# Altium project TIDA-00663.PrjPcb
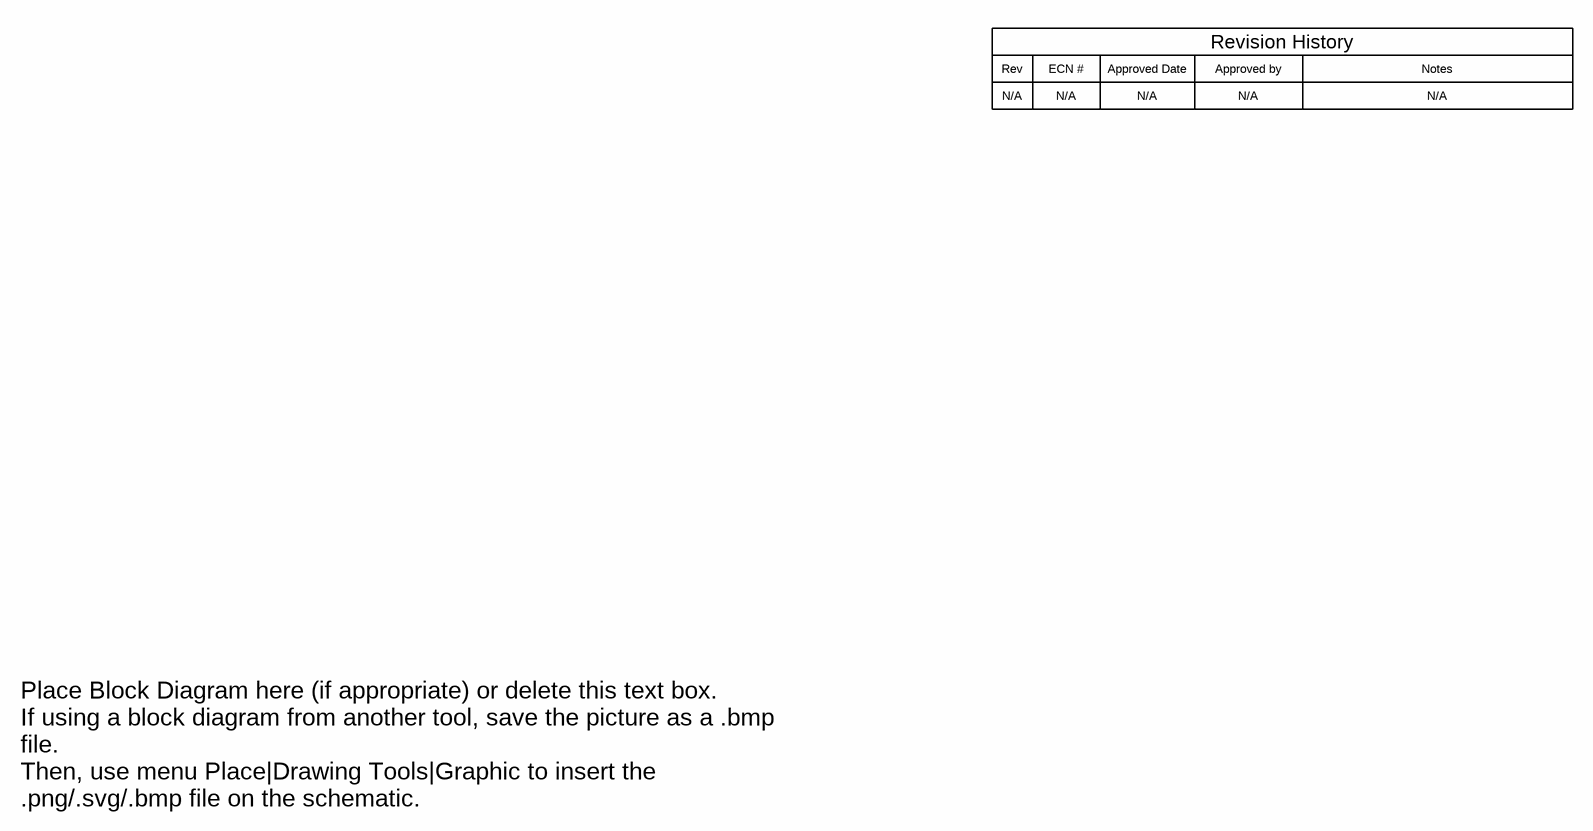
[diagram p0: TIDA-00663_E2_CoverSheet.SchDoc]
CopyrightYear: 2016; PCB_Layout: GCD; PCB_Rev: E2; PRJ_Customer: Public Release; PRJ_Engineer: Matthieu Chevrier; PRJ_Number: TIDA-00663; PRJ_Title: LIDAR; SCH_Rev: E2; TechSupport: http://www.ti.com/support; TID: TIDA-00663
4 sheets, 73 parts. Net scope: global (net labels, ports and power ports of the same name join across sheets).
Board file: TIDA-00663_E2_PCB.PcbDoc
Sheets:
  TIDA-00663_E2_CoverSheet.SchDoc
  TIDA-00663_E2_time_measure_shi.SchDoc
  TIDA-00663_E2_EVM_Hardware.SchDoc
  TIDA-00663_E2_DesignForTest.SchDoc

## Sheet TIDA-00663_E2_CoverSheet.SchDoc
size 431 x 279 mm; Date: Not shown in title block; ApprovedBy: Not shown in title block; CheckedBy: Not shown in title block; Author: Not shown in title block; CompanyName: Not shown in title block; Engineer: Not shown in title block; Organization: Not shown in title block; Address1: Not shown in title block; Address2: Not shown in title block; Address3: Not shown in title block; Address4: Not shown in title block; DocumentNumber: 1; Revision: Use project parameter SCH_Rev; SheetNumber: 1; SheetTotal: 3; PageSetup: Record=PageOptions¦CenterHorizontal=True¦CenterVertical=True¦PrintScale=1.00¦XCorrection=1.00¦YCorrection=1.00¦PrintKind=0¦BorderSize=5000000¦LeftOffset=0¦BottomOffset=0¦Orientation=2¦PaperLength=1000¦PaperWidth=1000¦Scale=100¦PaperSource=15¦PrintQuality=600¦MediaType=1¦DitherType=10¦PaperKind=Letter¦PrintScaleMode=1

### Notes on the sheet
- Rev
- N/A
- ECN #
- Approved Date
- Approved by
- Revision History
- Notes
- Place Block Diagram here (if appropriate) or delete this text box.
  If using a block diagram from another tool, save the picture as a .bmp file.
  Then, use menu Place|Drawing Tools|Graphic to insert the .png/.svg/.bmp file on the schematic.

## Sheet TIDA-00663_E2_time_measure_shi.SchDoc
size 431 x 279 mm; Date: Not shown in title block; ApprovedBy: Not shown in title block; CheckedBy: Not shown in title block; Author: Not shown in title block; CompanyName: Not shown in title block; Engineer: Not shown in title block; Organization: Not shown in title block; Address1: Not shown in title block; Address2: Not shown in title block; Address3: Not shown in title block; Address4: Not shown in title block; DocumentNumber: 1; Revision: Use project parameter SCH_Rev; SheetNumber: 2; SheetTotal: 3; PageSetup: Record=PageOptions¦CenterHorizontal=True¦CenterVertical=True¦PrintScale=0.80¦XCorrection=1.00¦YCorrection=1.00¦PrintKind=0¦BorderSize=5000000¦LeftOffset=0¦BottomOffset=0¦Orientation=2¦PaperLength=4200¦PaperWidth=2970¦Scale=100¦PaperSource=7¦PrintQuality=600¦MediaType=1¦DitherType=10¦PrintScaleMode=1¦PaperKind=A3¦PaperIndex=8
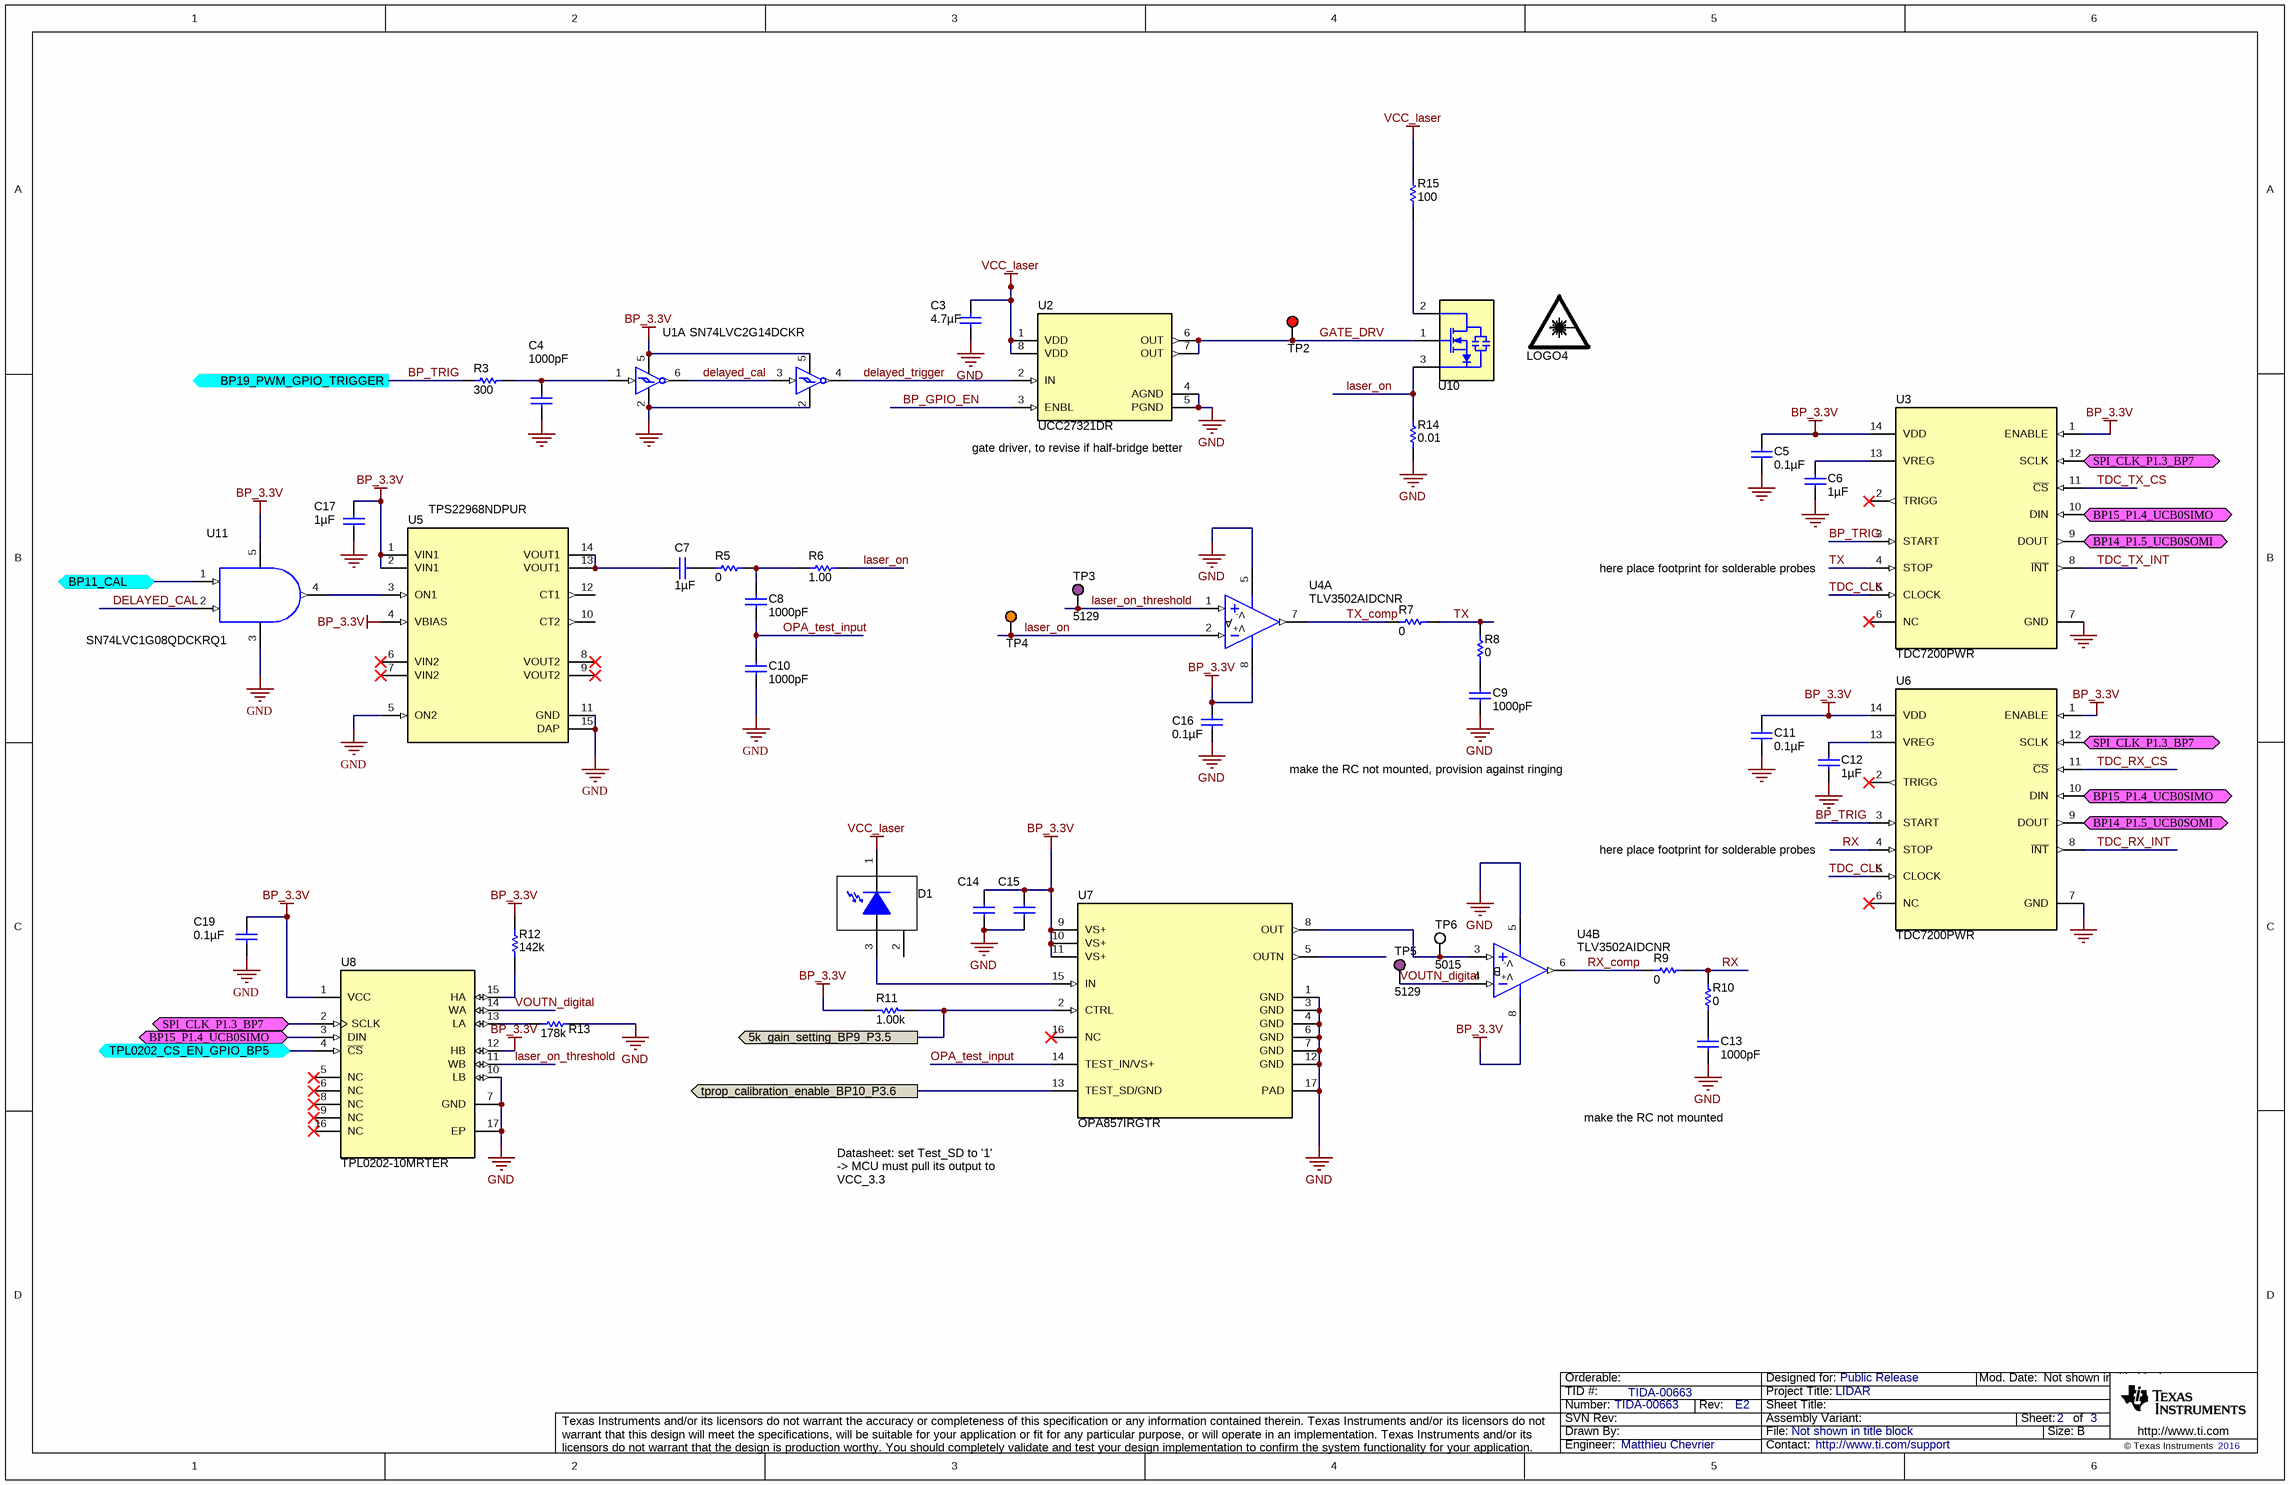
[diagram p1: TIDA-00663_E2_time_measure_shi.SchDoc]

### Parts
C3  ValueDisplayed: 4.7µF  [1206]  (hidden comment: GRM319R61H475KA12)
C4  ValueDisplayed: 1000pF  [0603]  (hidden comment: GRM1885C1H102FA01J)
C5  ValueDisplayed: 0.1µF  [0603]  (hidden comment: 0603YC104JAT2A)
C6  ValueDisplayed: 1µF  [0603]  (hidden comment: EMK107B7105KA-T)
C7  ValueDisplayed: 1µF  [0805_HV]  (hidden comment: 0805YD105KAT2A)
C8  ValueDisplayed: 1000pF  [0603]  (hidden comment: C0603X102K5RACTU)
C9  ValueDisplayed: 1000pF  [0603]  (hidden comment: C0603X102K5RACTU)
C10  ValueDisplayed: 1000pF  [0603]  (hidden comment: C0603X102K5RACTU)
C11  ValueDisplayed: 0.1µF  [0603]  (hidden comment: 0603YC104JAT2A)
C12  ValueDisplayed: 1µF  [0603]  (hidden comment: EMK107B7105KA-T)
C13  ValueDisplayed: 1000pF  [0603]  (hidden comment: C0603X102K5RACTU)
C14  GRM155R61A104KA01D  [0402]  (value not drawn)
C15  GRM155R61A104KA01D  [0402]  (value not drawn)
C16  ValueDisplayed: 0.1µF  [0603]  (hidden comment: 0603YC104JAT2A)
C17  ValueDisplayed: 1µF  [0603]  (hidden comment: EMK107B7105KA-T)
C19  ValueDisplayed: 0.1µF  [0603]  (hidden comment: 0603YC104JAT2A)
D1  SFH 2400FA-Z  [SFH2400FA]  (value not drawn)
LOGO4  LASER RADIATION  [LaserWarning_Small]  (value not drawn)  (no BOM)
R3  ValueDisplayed: 300  [0805_HV]  (hidden comment: ERJ-6GEYJ301V)
R5  ValueDisplayed: 0  [0805_HV]  (hidden comment: MCR10EZHJ000)
R6  ValueDisplayed: 1.00  [0805_HV]  (hidden comment: CRCW08051R00FKEA)
R7  ValueDisplayed: 0  [0805_HV]  (hidden comment: CRCW08050000Z0EA)
R8  ValueDisplayed: 0  [0805_HV]  (hidden comment: CRCW08050000Z0EA)
R9  ValueDisplayed: 0  [0805_HV]  (hidden comment: CRCW08050000Z0EA)
R10  ValueDisplayed: 0  [0805_HV]  (hidden comment: CRCW08050000Z0EA)
R11  ValueDisplayed: 1.00k  [0603]  (hidden comment: CRCW06031K00FKEA)
R12  ValueDisplayed: 142k  [0805_HV]  (hidden comment: RT0805BRD07142KL)
R13  ValueDisplayed: 178k  [0805_HV]  (hidden comment: RT0805BRD07178KL)
R14  ValueDisplayed: 0.01  [0805_HV]  (hidden comment: WSL0805R0100FEA18)
R15  ValueDisplayed: 100  [1206]  (hidden comment: TNPW1206100RBEEA)
TP2  5005  [Keystone5005]  (value not drawn)
TP3  5129  [Keystone5129]
TP4  5013  [Keystone5013]  (value not drawn)
TP5  5129  [Keystone5129]
TP6  5015  [Testpoint_Keystone_Miniature]
U1  SN74LVC2G14DCKR  [DCK0006A_N]  (parts A,B of 2)
U2  UCC27321DR  [D0008A_N]
U3  TDC7200PWR  [PW0014A_N]
U4  TLV3502AIDCNR  [DCN0008A_N]  (parts A,B of 2)
U5  TPS22968NDPUR  [DPU0014A]
U6  TDC7200PWR  [PW0014A_N]
U7  OPA857IRGTR  [RGT0016A]
U8  TPL0202-10MRTER  [RTE0016D]
U10  SPL LL90_3  [SPLLL90_3]  (value not drawn)
U11  SN74LVC1G08QDCKRQ1  [DCK0005A_N]

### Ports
5k_gain_setting_BP9_P3.5, BP11_CAL (bidir), BP14_P1.5_UCB0SOMI (bidir), BP15_P1.4_UCB0SIMO (bidir), BP19_PWM_GPIO_TRIGGER (out), SPI_CLK_P1.3_BP7 (bidir), TPL0202_CS_EN_GPIO_BP5 (bidir), tprop_calibration_enable_BP10_P3.6

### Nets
BP_3.3V: C5.1 C11.1 C14.1 C15.1 C16.1 C17.1 C19.1 R11.2 R12.2 U1.5(VCC) U3.1(ENABLE) U3.14(VDD) U4.8(V+) U5.1(VIN1) U5.2(VIN1) U5.4(VBIAS) U6.1(ENABLE) U6.14(VDD) U7.9(VS+) U7.10(VS+) U7.11(VS+) U8.1(VCC) U8.12(HB) U11.5(V+)
GND: C3.2 C4.2 C5.2 C6.2 C9.2 C10.2 C11.2 C12.2 C13.2 C14.2 C15.2 C16.2 C17.2 C19.2 R13.2 R14.1 U1.2(GND) U2.4(AGND) U2.5(PGND) U3.7(GND) U4.5(V-) U5.5(ON2) U5.11(GND) U5.15(DAP) U6.7(GND) U7.1(GND) U7.3(GND) U7.4(GND) U7.6(GND) U7.7(GND) U7.12(GND) U7.17(PAD) U8.7(GND) U8.10(LB) U8.17(EP) U11.3(V-)
VCC_laser: C3.1 D1.1(C) R15.2 U2.1(VDD) U2.8(VDD)
5k_gain_setting_BP9_P3.5: R11.1 U7.2(CTRL) ; port 5k_gain_setting_BP9_P3.5
BP11_CAL: U11.1(A) ; port BP11_CAL
BP14_P1.5_UCB0SOMI: U3.9(DOUT) U6.9(DOUT) ; port BP14_P1.5_UCB0SOMI
BP15_P1.4_UCB0SIMO: U3.10(DIN) U6.10(DIN) U8.3(DIN) ; port BP15_P1.4_UCB0SIMO
BP_GPIO_EN: U2.3(ENBL)
BP_TRIG: R3.1 U3.3(START) U6.3(START) ; port BP19_PWM_GPIO_TRIGGER
delayed_cal: U1.3(2A) U1.6(1Y) U11.2(B)
delayed_trigger: U1.4(2Y) U2.2(IN)
GATE_DRV: TP2.1 U2.6(OUT) U2.7(OUT) U10.1(VG)
laser_on: R6.2 R14.2 TP4.1 U4.2(-IN_A) U10.3(GND)
laser_on_threshold: TP3.1 U4.1(+IN_A) U8.11(WB)
OPA_test_input: C8.2 C10.1 U7.14(TEST_IN/VS+)
RX: R9.2 R10.2 U6.4(STOP)
RX_comp: R9.1 U4.6(OUT_B)
SPI_CLK_P1.3_BP7: U3.12(SCLK) U6.12(SCLK) U8.2(SCLK) ; port SPI_CLK_P1.3_BP7
TDC_CLK: U3.5(CLOCK) U6.5(CLOCK)
TDC_RX_CS: U6.11(~{CS})
TDC_RX_INT: U6.8(~{INT})
TDC_TX_CS: U3.11(~{CS})
TDC_TX_INT: U3.8(~{INT})
TPL0202_CS_EN_GPIO_BP5: U8.4(~{CS}) ; port TPL0202_CS_EN_GPIO_BP5
tprop_calibration_enable_BP10_P3.6: U7.13(TEST_SD/GND) ; port tprop_calibration_enable_BP10_P3.6
TX: R7.2 R8.2 U3.4(STOP)
TX_comp: R7.1 U4.7(OUT_A)
VOUTN_digital: TP5.1 U4.4(-IN_B) U8.14(WA)
NetC4_1: C4.1 R3.2 U1.1(1A)
NetC6_1: C6.1 U3.13(VREG)
NetC7_1: C7.1 R5.1
NetC7_2: C7.2 U5.13(VOUT1) U5.14(VOUT1)
NetC8_1: C8.1 R5.2 R6.1
NetC9_1: C9.1 R8.1
NetC12_1: C12.1 U6.13(VREG)
NetC13_1: C13.1 R10.1
NetD1_3: D1.3(A) U7.15(IN)
NetR12_1: R12.1 U8.15(HA)
NetR13_1: R13.1 U8.13(LA)
NetR15_1: R15.1 U10.2(VC)
NetTP6_1: TP6.1 U4.3(+IN_B) U7.8(OUT)
NetU5_3: U5.3(ON1) U11.4(Y)

Not connected (* = marked no-connect by the designer): D1 2(NC); U3 2(TRIGG)* 6(NC)*; U5 6(VIN2)* 7(VIN2)* 8(VOUT2)* 9(VOUT2)* 10(CT2) 12(CT1); U6 2(TRIGG)* 6(NC)*; U7 5(OUTN) 16(NC)*; U8 5(NC)* 6(NC)* 8(NC)* 9(NC)* 16(NC)*

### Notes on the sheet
- (near U2) gate driver, to revise if half-bridge better
- here place footprint for solderable probes
- make the RC not mounted, provision against ringing
- make the RC not mounted
- Datasheet: set Test_SD to '1'
  -> MCU must pull its output to VCC_3.3

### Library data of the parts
C3 = GRM319R61H475KA12: CAP, CERM, 4.7 µF, 50 V, +/- 10%, X5R, 1206; Manufacturer: MuRata; Polarized: N; CompType: Capacitor; Value: 4.7uF; U/M: EA; Cap_F: 0.0000047; Tolerance_%: 10; Value1: Unknown; VDC_V: 50; Value2: 50V; TaMin_C: -55; TaMax_C: 85; AEC Category: Q200
C4 = GRM1885C1H102FA01J: CAP, CERM, 1000 pF, 50 V, +/- 1%, C0G/NP0, 0603; Manufacturer: MuRata; Polarized: N; CompType: Capacitor; Value: 1000pF; U/M: EA; Cap_F: 0.000000001; Tolerance_%: 1; Value1: Unknown; VDC_V: 50; Value2: 50V; TaMin_C: -55; TaMax_C: 125; AEC Category: Q200
C5 C11 C16 C19 = 0603YC104JAT2A: CAP, CERM, 0.1 µF, 16 V, +/- 5%, X7R, 0603; Manufacturer: AVX; Polarized: N; CompType: Capacitor; Value: 0.1uF; U/M: EA; Cap_F: 0.0000001; Tolerance_%: 5; ESR_ohm: 0.039; Value1: 0.039 ohm; VDC_V: 16; Value2: 16V; TaMin_C: -55; TaMax_C: 125; AEC Category: Q200
C6 C12 C17 = EMK107B7105KA-T: CAP, CERM, 1 µF, 16 V, +/- 10%, X7R, 0603; Manufacturer: Taiyo Yuden; Polarized: N; CompType: Capacitor; Value: 1uF; U/M: EA; Cap_F: 0.000001; Tolerance_%: 10; Value1: Unknown; VDC_V: 16; Value2: 16V; TaMin_C: -55; TaMax_C: 85; AEC Category: Q200
C7 = 0805YD105KAT2A: CAP, CERM, 1 µF, 16 V, +/- 10%, X5R, 0805; Manufacturer: AVX; Polarized: N; CompType: Capacitor; Value: 1uF; U/M: EA; Cap_F: 0.000001; Tolerance_%: 10; ESR_ohm: 0.012; Value1: 0.012 ohm; VDC_V: 16; Value2: 16V; TaMin_C: -55; TaMax_C: 85; Cap_Case: 0805; AEC Category: Q200
C8-C10 C13 = C0603X102K5RACTU: CAP, CERM, 1000 pF, 50 V, +/- 10%, X7R, 0603; Manufacturer: Kemet; Polarized: N; CompType: Capacitor; Value: 1000pF; U/M: EA; Cap_F: 0.000000001; Tolerance_%: 10; Value1: Unknown; VDC_V: 50; Value2: 50V; TaMin_C: -55; TaMax_C: 125; AEC Category: Q200
C14 C15 = GRM155R61A104KA01D: CAP, CERM, 0.1 µF, 10 V, +/- 10%, X5R, 0402; Manufacturer: MuRata; Polarized: N; CompType: Capacitor; Value: 0.1uF; U/M: EA; Cap_F: 0.0000001; Tolerance_%: 10; Value1: Unknown; Value2: 10V; TaMin_C: -55; TaMax_C: 85; AEC Category: Q200
D1 = SFH 2400FA-Z: Silicon PIN Photodiode, SMD; Manufacturer: OSRAM; SymbolCreator: Altium
LOGO4 = Laser_Warning: Laser Warning Symbol; SymbolCreator: a0412235
R3 = ERJ-6GEYJ301V: RES, 300, 5%, 0.125 W, 0805; Manufacturer: Panasonic; CompType: Resistor; Value: 300; Value_Code: 300R; Tolerance_%: 5; Power_W: 0.125; Value2: 0.125W; VDC_V: 150; TempCo: 200 ppm/C; EIA_Code: E24; U/M: EA; AEC Category: Q200
R5 = MCR10EZHJ000: RES, 0, 5%, 0.125 W, 0805; Manufacturer: Rohm; CompType: Resistor; Value: 0; Value_Code: 0000; Tolerance_%: 5; Power_W: 0.125; Value2: 0.125W; VDC_V: 150; TempCo: 400 ppm/C; EIA_Code: E24; U/M: EA; AEC Category: Q200
R6 = CRCW08051R00FKEA: RES, 1.00, 1%, 0.125 W, 0805; Manufacturer: Vishay-Dale; CompType: Resistor; Value: 1.00; Res_ohm: 1; Value_Code: 1R00; Power_W: 0.125; Value2: 0.125W; VDC_V: 150; TempCo: 100 ppm/C; EIA_Code: E96; U/M: EA; AEC Category: Q200
R7-R10 = CRCW08050000Z0EA: RES, 0, 5%, 0.125 W, 0805; Manufacturer: Vishay-Dale; CompType: Resistor; Value: 0; Value_Code: 0000; Tolerance_%: 5; Power_W: 0.125; Value2: 0.125W; VDC_V: 150; TempCo: 200 ppm/C; EIA_Code: E24; U/M: EA; AEC Category: Q200
R11 = CRCW06031K00FKEA: RES, 1.00 k, 1%, 0.1 W, 0603; Manufacturer: Vishay-Dale; CompType: Resistor; Value: 1.00k; Res_ohm: 1000; Value_Code: 1k00; Tolerance_%: 1; Power_W: 0.1; Value2: 0.1W; VDC_V: 75; TempCo: 100 ppm/C; EIA_Code: E96; U/M: EA; AEC Category: Q200
R12 = RT0805BRD07142KL: RES, 142 k, 0.1%, 0.125 W, 0805; Manufacturer: Yageo America; CompType: Resistor; Value: 142k; Res_ohm: 142000; Tolerance_%: 0.1; Power_W: 0.125; Value2: 0.125W; VDC_V: 150; TempCo: 25 ppm/C; EIA_Code: E192; U/M: EA; AEC Category: Q200
R13 = RT0805BRD07178KL: RES, 178 k, 0.1%, 0.125 W, 0805; Manufacturer: Yageo America; CompType: Resistor; Value: 178k; Res_ohm: 178000; Tolerance_%: 0.1; Power_W: 0.125; Value2: 0.125W; VDC_V: 150; TempCo: 25 ppm/C; EIA_Code: E192; U/M: EA; AEC Category: Q200
R14 = WSL0805R0100FEA18: RES, 0.01, 1%, 0.25 W, 0805; Manufacturer: Vishay-Dale; CompType: Resistor; Value: 0.01; Value_Code: R010; Tolerance_%: 1; Power_W: 0.25; Value2: 0.25W; TempCo: 75 ppm/C; EIA_Code: E96; U/M: EA; AEC Category: Q200
R15 = TNPW1206100RBEEA: RES, 100, 0.1%, 0.25 W, 1206; Manufacturer: Vishay-Dale; CompType: Resistor; Value: 100; Value_Code: 100R; Tolerance_%: 0.1; Power_W: 0.25; Value2: 0.25W; VDC_V: 200; TempCo: 25 ppm/C; EIA_Code: E192; U/M: EA; AEC Category: Q200
TP2 = 5005: Test Point, Compact, Red, TH; Manufacturer: Keystone; CompType: Test Point Loop; ContactFinish: Silver
TP3 TP5 = 5129: Test Point, Multipurpose, Purple, TH; Manufacturer: Keystone; SymbolCreator: a0412235; CompType: Test Point Loop; ContactFinish: Silver
TP4 = 5013: Test Point, Multipurpose, Orange, TH; Manufacturer: Keystone; CompType: Test Point Loop; ContactFinish: Silver
TP6 = 5015: Test Point, Miniature, SMT; Manufacturer: Keystone; CompType: Test Point Loop
U1 = SN74LVC2G14DCKR: Dual Schmitt-Trigger Inverter, DCK0006A; Alternate PartNumber: SN74LVC2G14DCKT; Manufacturer: Texas Instruments; SymbolCreator: a0411947; SizeX_mm: 2.1; SizeY_mm: 2; SizeZ_mm: 1.1; CompType: IC; U/M: EA
U2 = UCC27321DR: SINGLE 9-A HIGH SPEED LOW- SIDE MOSFET DRIVER WITH ENABLE, D0008A; Manufacturer: Texas Instruments; SymbolCreator: Altium; CompType: IC; U/M: EA
U3 U6 = TDC7200PWR: Time-to-Digital Converter for Water, Gas, Heat Flow Metering Applications, PW0016A; Manufacturer: Texas Instruments; SymbolCreator: a0411947; CompType: IC; U/M: EA
U4 = TLV3502AIDCNR: 4.5 ns Rail-to-Rail, High-Speed Comparator, DCN0008A; Alternate PartNumber: TLV3502AIDCNT; Manufacturer: Texas Instruments; SymbolCreator: Altium; CompType: IC; U/M: EA
U5 = TPS22968NDPUR: Dual Channel, Ultra-Low Resistance Load Switch, DPU0014A; Manufacturer: Texas Instruments; SymbolCreator: a0411947; SizeX_mm: 2; SizeY_mm: 3; SizeZ_mm: 0.8; CompType: IC; U/M: EA
U7 = OPA857IRGTR: Ultralow-Noise, Wideband, Selectable-Feedback Resistance Transimpedance Amplifier, RGT0016A; Alternate PartNumber: OPA857IRGTT; Manufacturer: Texas Instruments; SymbolCreator: Altium; CompType: IC; U/M: EA
U8 = TPL0202-10MRTER: 256-TAPS DUAL CHANNEL DIGITAL POTENTIOMETER WITH SPI INTERFACE AND NONVOLATILE MEMORY, RTE0016D; Manufacturer: Texas Instruments; SymbolCreator: Altium; CompType: IC; U/M: EA
U10 = SPL LL90_3: Hybrid Pulsed Laser Diode with Integrated Driver Stage 70 W Peak Power, TH; Manufacturer: OSRAM; SymbolCreator: Altium
U11 = SN74LVC1G08QDCKRQ1: Single 2-Input Positive-AND Gate, DCK0005A; Manufacturer: Texas Instruments; CompType: IC; U/M: EA

## Sheet TIDA-00663_E2_EVM_Hardware.SchDoc
size 431 x 279 mm; Date: Not shown in title block; ApprovedBy: Not shown in title block; CheckedBy: Not shown in title block; Author: Not shown in title block; CompanyName: Not shown in title block; Engineer: Not shown in title block; Organization: Not shown in title block; Address1: Not shown in title block; Address2: Not shown in title block; Address3: Not shown in title block; Address4: Not shown in title block; DocumentNumber: 1; Revision: Use project parameter SCH_Rev; SheetNumber: 3; SheetTotal: 3; PageSetup: Record=PageOptions¦CenterHorizontal=True¦CenterVertical=True¦PrintScale=1.00¦XCorrection=1.00¦YCorrection=1.00¦PrintKind=0¦BorderSize=5000000¦LeftOffset=0¦BottomOffset=0¦Orientation=2¦PaperLength=1000¦PaperWidth=1000¦Scale=100¦PaperSource=15¦PrintQuality=600¦MediaType=1¦DitherType=10¦PaperKind=Letter¦PrintScaleMode=1
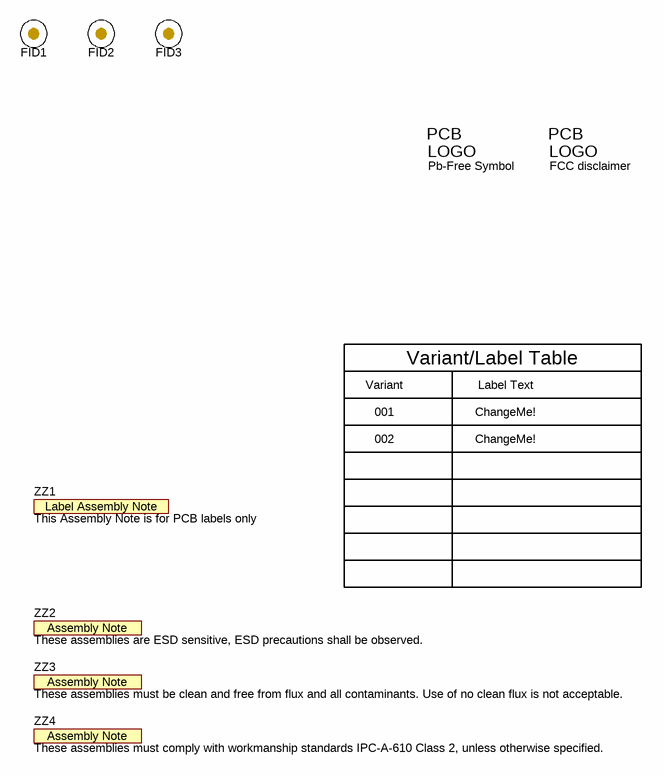
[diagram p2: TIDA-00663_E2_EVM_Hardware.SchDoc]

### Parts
FID1  Fiducial  [Fiducial10-20]  (value not drawn)
FID2  Fiducial  [Fiducial10-20]  (value not drawn)
FID3  Fiducial  [Fiducial10-20]  (value not drawn)
Logo2  Pb-Free Symbol  [Pb-Free_Overlay_Small]  (no BOM)
Logo3  FCC disclaimer  [FCC_disclaimer]  (no BOM)
ZZ1  This Assembly Note is for PCB labels only  [AssemblyNoteLabel]  (no BOM)
ZZ2  These assemblies are ESD sensitive, ESD precautions shall be observed.  [AssemblyNote]  (no BOM)
ZZ3  These assemblies must be clean and free from flux and all contaminants. Use of no clean flux is not acceptable.  [AssemblyNote]  (no BOM)
ZZ4  These assemblies must comply with workmanship standards IPC-A-610 Class 2, unless otherwise specified.  [AssemblyNote]  (no BOM)

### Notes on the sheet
- Variant
- Variant/Label Table
- Label Text
- 001
- 002
- ChangeMe!

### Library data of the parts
FID1-FID3 = Fiducial: Fiducial mark.  There is nothing to buy or mount.; SymbolCreator: codlsc
Logo2 = Pb-Free: SymbolCreator: a0412235
Logo3 = FCC_disclaimer: SymbolCreator: codlsc
ZZ1 = AssemblyNoteLabel: SymbolCreator: a0412235
ZZ2-ZZ4 = AssemblyNote: SymbolCreator: codlsc

## Sheet TIDA-00663_E2_DesignForTest.SchDoc
size 431 x 279 mm; Date: Not shown in title block; ApprovedBy: Not shown in title block; CheckedBy: Not shown in title block; Author: Not shown in title block; CompanyName: Not shown in title block; Engineer: Not shown in title block; Organization: Not shown in title block; Address1: Not shown in title block; Address2: Not shown in title block; Address3: Not shown in title block; Address4: Not shown in title block; DocumentNumber: 3; Revision: Use project parameter SCH_Rev; SheetNumber: 3; SheetTotal: 4; PageSetup: Record=PageOptions¦CenterHorizontal=True¦CenterVertical=True¦PrintScale=1.00¦XCorrection=1.00¦YCorrection=1.00¦PrintKind=0¦BorderSize=5000000¦LeftOffset=0¦BottomOffset=0¦Orientation=2¦PaperLength=1000¦PaperWidth=1000¦Scale=100¦PaperSource=15¦PrintQuality=600¦MediaType=1¦DitherType=10¦PaperKind=Letter¦PrintScaleMode=1
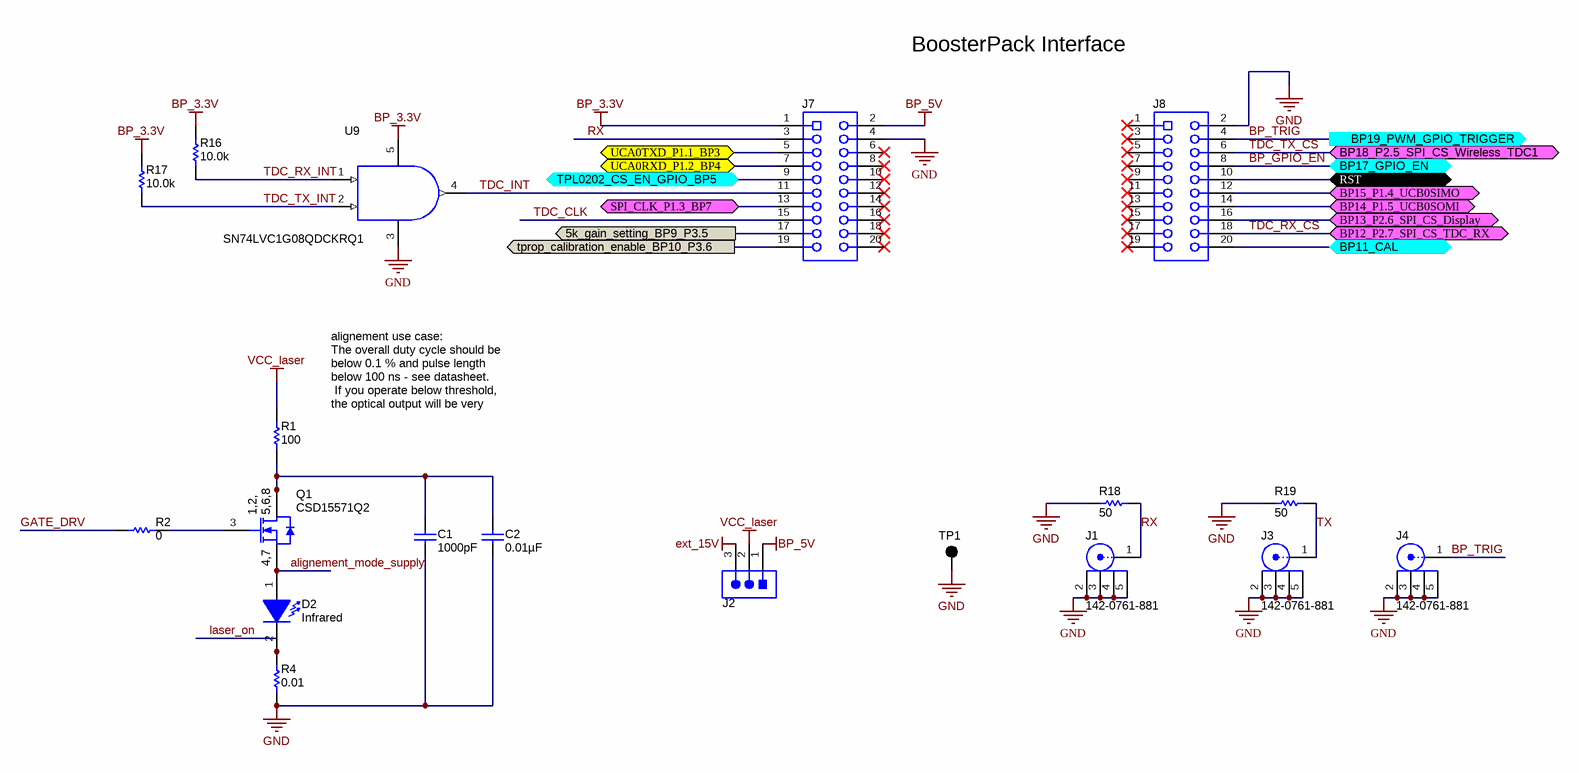
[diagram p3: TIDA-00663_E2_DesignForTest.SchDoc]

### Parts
C1  ValueDisplayed: 1000pF  [1206]  (hidden comment: 12061A102FAT2A)
C2  ValueDisplayed: 0.01µF  [0603]  (hidden comment: C1608X7R2A103M)
D2  value Infrared  [SPL_PL90_3_IR]  (hidden comment: SPL PL90_3)
J1  142-0761-881  [Johnson_142-0761-881]
J2  61300311121  [WURTH_61300311121]  (value not drawn)
J3  142-0761-881  [Johnson_142-0761-881]
J4  142-0761-881  [Johnson_142-0761-881]
J7  SSW-110-23-F-D  [CONN_SSW-110-23-F-D]  (value not drawn)
J8  SSW-110-23-F-D  [CONN_SSW-110-23-F-D]  (value not drawn)
Q1  CSD15571Q2  [TRANS_NexFET_Q2]
R1  ValueDisplayed: 100  [1206]  (hidden comment: TNPW1206100RBEEA)
R2  ValueDisplayed: 0  [0805_HV]  (hidden comment: MCR10EZPJ000)
R4  ValueDisplayed: 0.01  [0805_HV]  (hidden comment: WSL0805R0100FEA18)
R16  ValueDisplayed: 10.0k  [0603]  (hidden comment: CRCW060310K0FKEA)
R17  ValueDisplayed: 10.0k  [0603]  (hidden comment: CRCW060310K0FKEA)
R18  ValueDisplayed: 50  [0603]  (hidden comment: CRCW060350R0FKEA)
R19  ValueDisplayed: 50  [0603]  (hidden comment: CRCW060350R0FKEA)
TP1  5006  [Keystone5006]  (value not drawn)
U9  SN74LVC1G08QDCKRQ1  [DCK0005A_N]

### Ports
5k_gain_setting_BP9_P3.5, BP11_CAL (bidir), BP12_P2.7_SPI_CS_TDC_RX (bidir), BP13_P2.6_SPI_CS_Display (bidir), BP14_P1.5_UCB0SOMI (bidir), BP15_P1.4_UCB0SIMO (bidir), BP17_GPIO_EN (bidir), BP18_P2.5_SPI_CS_Wireless_TDC1 (bidir), BP19_PWM_GPIO_TRIGGER (out), RST (bidir), SPI_CLK_P1.3_BP7 (bidir), TPL0202_CS_EN_GPIO_BP5 (bidir), tprop_calibration_enable_BP10_P3.6, UCA0RXD_P1.2_BP4 (bidir), UCA0TXD_P1.1_BP3 (bidir)

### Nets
BP_3.3V: J7.1 R16.2 R17.2 U9.5(V+)
BP_5V: J2.1 J7.2
ext_15V: J2.3
GND: C1.2 C2.2 J1.2 J1.3 J1.4 J1.5 J3.2 J3.3 J3.4 J3.5 J4.2 J4.3 J4.4 J4.5 J7.4 J8.2 R4.1 R18.1 R19.1 TP1.1 U9.3(V-)
VCC_laser: J2.2 R1.2
5k_gain_setting_BP9_P3.5: J7.17 ; port 5k_gain_setting_BP9_P3.5
alignement_mode_supply: D2.1(A) Q1.4(S) Q1.7(S)
BP11_CAL: J8.20 ; port BP11_CAL
BP13_P2.6_SPI_CS_Display: J8.16 ; port BP13_P2.6_SPI_CS_Display
BP14_P1.5_UCB0SOMI: J8.14 ; port BP14_P1.5_UCB0SOMI
BP15_P1.4_UCB0SIMO: J8.12 ; port BP15_P1.4_UCB0SIMO
BP_GPIO_EN: J8.8 ; port BP17_GPIO_EN
BP_TRIG: J4.1 J8.4 ; port BP19_PWM_GPIO_TRIGGER
GATE_DRV: R2.1
laser_on: D2.2(K) R4.2
RST: J8.10 ; port RST
RX: J1.1 J7.3 R18.2
SPI_CLK_P1.3_BP7: J7.13 ; port SPI_CLK_P1.3_BP7
TDC_CLK: J7.15
TDC_INT: J7.11 U9.4(Y)
TDC_RX_CS: J8.18 ; port BP12_P2.7_SPI_CS_TDC_RX
TDC_RX_INT: R16.1 U9.1(A)
TDC_TX_CS: J8.6 ; port BP18_P2.5_SPI_CS_Wireless_TDC1
TDC_TX_INT: R17.1 U9.2(B)
TPL0202_CS_EN_GPIO_BP5: J7.9 ; port TPL0202_CS_EN_GPIO_BP5
tprop_calibration_enable_BP10_P3.6: J7.19 ; port tprop_calibration_enable_BP10_P3.6
TX: J3.1 R19.2
UCA0RXD_P1.2_BP4: J7.7 ; port UCA0RXD_P1.2_BP4
UCA0TXD_P1.1_BP3: J7.5 ; port UCA0TXD_P1.1_BP3
NetC1_1: C1.1 C2.1 Q1.1(D) Q1.2(D) Q1.5(D) Q1.6(D) Q1.8(D) R1.1
NetQ1_3: Q1.3(G) R2.2

Not connected (* = marked no-connect by the designer): J7 6* 8* 10* 12* 14* 16* 18* 20*; J8 1* 3* 5* 7* 9* 11* 13* 15* 17* 19*

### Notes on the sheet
- BoosterPack Interface
- alignement use case:
  The overall duty cycle should be below 0.1 % and pulse length below 100 ns - see datasheet.
  If you operate below threshold, the optical output will be very very low…almost zereo…
  I recommend to do some low duty cycle pulsing with e.g. 2 Amps for alignment (threshold < 1 Amp).

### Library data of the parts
C1 = 12061A102FAT2A: CAP, CERM, 1000 pF, 100 V, +/- 1%, C0G/NP0, 1206; Manufacturer: AVX; Polarized: N; CompType: Capacitor; Value: 1000pF; U/M: EA; Cap_F: 0.000000001; Tolerance_%: 1; ESR_ohm: 0.238; Value1: 0.238 ohm; VDC_V: 100; Value2: 100V; TaMin_C: -55; TaMax_C: 125; AEC Category: Q200
C2 = C1608X7R2A103M: CAP, CERM, 0.01 µF, 100 V, +/- 20%, X7R, 0603; Manufacturer: TDK; Polarized: N; CompType: Capacitor; Value: 0.01uF; U/M: EA; Cap_F: 0.00000001; Tolerance_%: 20; ESR_ohm: 0.0661; Value1: 0.0661 ohm; VDC_V: 100; Value2: 100V; TaMin_C: -55; TaMax_C: 125; AEC Category: Q200
D2 = SPL PL90_3: LED, Infrared, TH; Manufacturer: OSRAM; Vf_V: 9; Value2: 9V; Io_A: 30; Vr_V: 3; Tjmax_C: 85; Power_TotalModule: 75; Value1: 75W; SizeAreaWB_mm2: 57.33; SizeArea_mm2: 31.03; SizeX_mm: 5.35; SizeY_mm: 5.8; SizeZ_mm: 8; U/M: EA
J1 J3 J4 = 142-0761-881: Connector, TH, End launch SMA 50 ohm; Manufacturer: Johnson; SymbolCreator: X0208326
J2 = 61300311121: Header, 2.54 mm, 3x1, Gold, TH; Manufacturer: Wurth Elektronik; SymbolCreator: a0799628
J7 J8 = SSW-110-23-F-D: Connector, Receptacle, 100mil, 10x2, Gold plated, TH; Manufacturer: Samtec; SymbolCreator: a0412235; U/M: EA
Q1 = CSD15571Q2: MOSFET, N-CH, 20 V, 10 A, SON 2x2mm; Manufacturer: Texas Instruments; Alternate Manufacturer: None; U/M: EA; ChType: N; Value: 20V; VdsMax_V: 20; Value1: 19.2 ohm; Rdson45_ohm: 19.2; Value2: 2.5 nC; QgTyp_nC: 2.5; IdsMax_A: 10; AEC Category: Q101
R1 = TNPW1206100RBEEA: as R15 on sheet TIDA-00663_E2_time_measure_shi
R2 = MCR10EZPJ000: RES, 0, 5%, 0.125 W, 0805; Manufacturer: Rohm; CompType: Resistor; Value: 0; Value_Code: 0000; Tolerance_%: 5; Power_W: 0.125; Value2: 0.125W; VDC_V: 150; TempCo: 400 ppm/C; EIA_Code: E24; U/M: EA; AEC Category: Q200
R4 = WSL0805R0100FEA18: as R14 on sheet TIDA-00663_E2_time_measure_shi
R16 R17 = CRCW060310K0FKEA: RES, 10.0 k, 1%, 0.1 W, 0603; Manufacturer: Vishay-Dale; CompType: Resistor; Value: 10.0k; Res_ohm: 10000; Value_Code: 10k0; Tolerance_%: 1; Power_W: 0.1; Value2: 0.1W; VDC_V: 75; TempCo: 100 ppm/C; SizeArea_mm2: 1.28; SizeX_mm: 1.6; SizeY_mm: 0.8; EIA_Code: E96; U/M: EA; AEC Category: Q200
R18 R19 = CRCW060350R0FKEA: RES, 50, 1%, 0.1 W, 0603; Manufacturer: Vishay-Dale; CompType: Resistor; Value: 50; Value_Code: 50R0; Tolerance_%: 1; Power_W: 0.1; Value2: 0.1W; VDC_V: 75; TempCo: 100 ppm/C; SizeArea_mm2: 1.28; SizeX_mm: 1.6; SizeY_mm: 0.8; U/M: EA; AEC Category: Q200
TP1 = 5006: Test Point, Compact, Black, TH; Manufacturer: Keystone; CompType: Test Point Loop; ContactFinish: Silver
U9 = SN74LVC1G08QDCKRQ1: as U11 on sheet TIDA-00663_E2_time_measure_shi

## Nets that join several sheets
BP_3.3V: TIDA-00663_E2_time_measure_shi (24 pins), TIDA-00663_E2_DesignForTest (J7.1 R16.2 R17.2 U9.5)
GND: TIDA-00663_E2_time_measure_shi (36 pins), TIDA-00663_E2_DesignForTest (21 pins)
VCC_laser: TIDA-00663_E2_time_measure_shi (5 pins), TIDA-00663_E2_DesignForTest (J2.2 R1.2)
5k_gain_setting_BP9_P3.5: TIDA-00663_E2_time_measure_shi (R11.1 U7.2), TIDA-00663_E2_DesignForTest (J7.17)
BP11_CAL: TIDA-00663_E2_time_measure_shi (U11.1), TIDA-00663_E2_DesignForTest (J8.20)
BP14_P1.5_UCB0SOMI: TIDA-00663_E2_time_measure_shi (U3.9 U6.9), TIDA-00663_E2_DesignForTest (J8.14)
BP15_P1.4_UCB0SIMO: TIDA-00663_E2_time_measure_shi (U3.10 U6.10 U8.3), TIDA-00663_E2_DesignForTest (J8.12)
BP_GPIO_EN: TIDA-00663_E2_time_measure_shi (U2.3), TIDA-00663_E2_DesignForTest (J8.8)
BP_TRIG: TIDA-00663_E2_time_measure_shi (R3.1 U3.3 U6.3), TIDA-00663_E2_DesignForTest (J4.1 J8.4)
GATE_DRV: TIDA-00663_E2_time_measure_shi (TP2.1 U2.6 U2.7 U10.1), TIDA-00663_E2_DesignForTest (R2.1)
laser_on: TIDA-00663_E2_time_measure_shi (5 pins), TIDA-00663_E2_DesignForTest (D2.2 R4.2)
RX: TIDA-00663_E2_time_measure_shi (R9.2 R10.2 U6.4), TIDA-00663_E2_DesignForTest (J1.1 J7.3 R18.2)
SPI_CLK_P1.3_BP7: TIDA-00663_E2_time_measure_shi (U3.12 U6.12 U8.2), TIDA-00663_E2_DesignForTest (J7.13)
TDC_CLK: TIDA-00663_E2_time_measure_shi (U3.5 U6.5), TIDA-00663_E2_DesignForTest (J7.15)
TDC_RX_CS: TIDA-00663_E2_time_measure_shi (U6.11), TIDA-00663_E2_DesignForTest (J8.18)
TDC_RX_INT: TIDA-00663_E2_time_measure_shi (U6.8), TIDA-00663_E2_DesignForTest (R16.1 U9.1)
TDC_TX_CS: TIDA-00663_E2_time_measure_shi (U3.11), TIDA-00663_E2_DesignForTest (J8.6)
TDC_TX_INT: TIDA-00663_E2_time_measure_shi (U3.8), TIDA-00663_E2_DesignForTest (R17.1 U9.2)
TPL0202_CS_EN_GPIO_BP5: TIDA-00663_E2_time_measure_shi (U8.4), TIDA-00663_E2_DesignForTest (J7.9)
tprop_calibration_enable_BP10_P3.6: TIDA-00663_E2_time_measure_shi (U7.13), TIDA-00663_E2_DesignForTest (J7.19)
TX: TIDA-00663_E2_time_measure_shi (R7.2 R8.2 U3.4), TIDA-00663_E2_DesignForTest (J3.1 R19.2)

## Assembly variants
TIDA-00663: not fitted C1 C2 D2 Q1 R1 R2 R4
